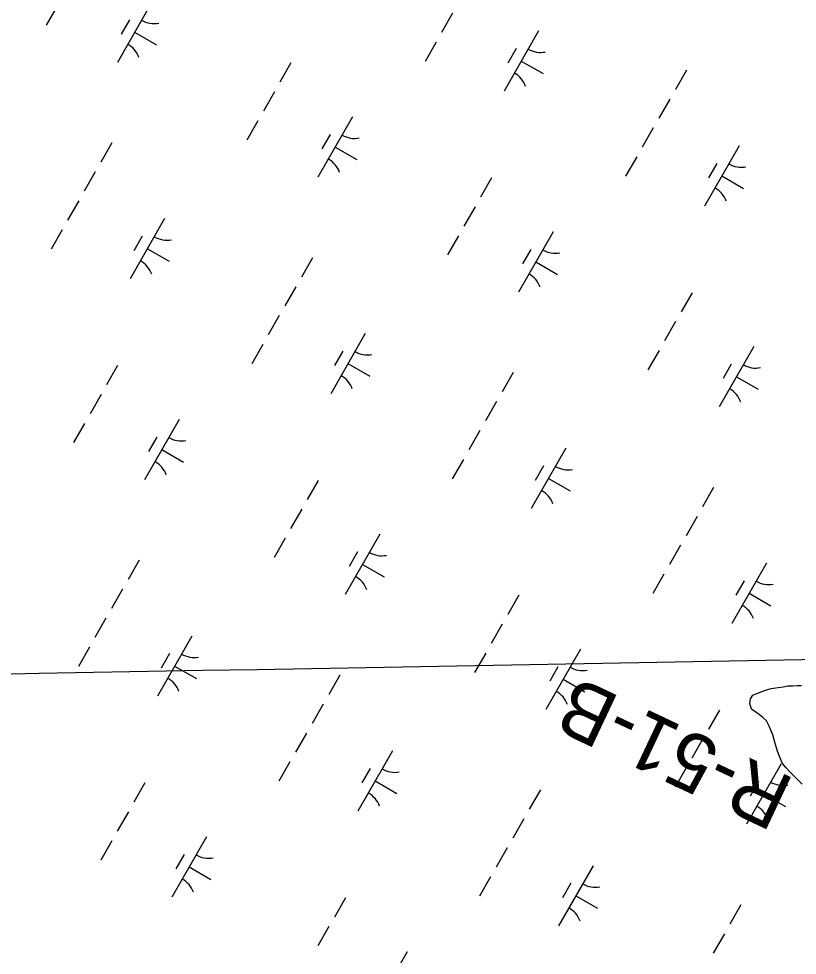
# Model space of a CAD drawing. Extents: x 3930721 to 3950824, y 220441 to 242861.
# Drawn here: x 3938703 to 3939263, y 229978 to 230653 of the extents above; entities that cross this region are included whole.
import ezdxf

# ---------------------------------------------------------------- set-up
doc = ezdxf.new("R2010")
doc.units = 0
for name, color, linetype in [('V-GRID-MAJR', 7, 'Continuous'), ('V-RIVR-RANG-IDEN', 7, 'Continuous'), ('V-TOPO-SHOR', 7, 'Continuous'), ('V-WETL-SWMP', 7, 'Continuous')]:
    doc.layers.add(name, color=color, linetype=linetype)

msp = doc.modelspace()

# ---------------------------------------------------------------- linework, layer by layer
at = {"layer": 'V-GRID-MAJR'}
msp.add_spline([(3935736.57, 230127.92), (3940756.95, 230218.14), (3946078.33, 230314.51), (3946614.64, 230324.26)], degree=3, dxfattribs=at)
at = {"layer": 'V-TOPO-SHOR'}
msp.add_lwpolyline([(3939263.36, 230104.8), (3939260.47, 230107.63), (3939257.84, 230110.21), (3939254.95, 230113.3), (3939252.32, 230116.39), (3939250.19, 230121.57), (3939248.58, 230125.97), (3939247.24, 230130.12), (3939246.43, 230133.49), (3939245.35, 230137.12), (3939244.02, 230140.48), (3939242.69, 230143.33), (3939240.83, 230147.21), (3939238.21, 230149.52), (3939235.85, 230151.58), (3939233.23, 230153.37), (3939230.09, 230155.68), (3939228.75, 230159.57), (3939229.23, 230162.95), (3939231.03, 230165.57), (3939235.17, 230167.43), (3939239.31, 230169.03), (3939244.24, 230170.38), (3939247.61, 230170.93), (3939252.8, 230171.77), (3939256.17, 230172.32), (3939259.81, 230172.36), (3939262.93, 230172.65), (3939266.05, 230172.68)], dxfattribs=at)
at = {"layer": 'V-WETL-SWMP'}
for p, q in [((3938730.49, 230661.75), (3938722.54, 230647.87)), ((3938798.61, 230664.56), (3938773.76, 230621.17)), ((3939015, 230656.64), (3939007.04, 230642.75)), ((3938782.48, 230651.91), (3938776.51, 230641.5)), ((3938786.19, 230642.87), (3938801.81, 230633.92)), ((3939076.82, 230643.79), (3939051.97, 230600.4)), ((3939003.07, 230635.81), (3938995.12, 230621.92)), ((3939060.68, 230631.13), (3939054.72, 230620.72)), ((3939064.4, 230622.09), (3939080.02, 230613.15)), ((3938898.69, 230620.74), (3938890.74, 230606.85)), ((3939183.19, 230615.62), (3939175.24, 230601.74)), ((3938886.76, 230599.91), (3938878.81, 230586.03)), ((3939171.26, 230594.8), (3939163.31, 230580.91)), ((3938942.95, 230581.9), (3938918.11, 230538.51)), ((3938874.83, 230579.08), (3938866.88, 230565.2)), ((3939159.34, 230573.97), (3939151.39, 230560.08)), ((3938926.82, 230569.24), (3938920.85, 230558.83)), ((3938769.79, 230563.19), (3938761.84, 230549.3)), ((3939221.16, 230561.12), (3939196.31, 230517.73)), ((3938930.53, 230560.2), (3938946.15, 230551.26)), ((3939147.41, 230553.14), (3939139.46, 230539.26)), ((3939205.03, 230548.47), (3939199.06, 230538.06)), ((3938757.86, 230542.36), (3938749.91, 230528.47)), ((3939043.03, 230538.07), (3939035.08, 230524.19)), ((3939208.74, 230539.43), (3939224.36, 230530.48)), ((3938745.94, 230521.53), (3938737.98, 230507.65)), ((3939031.1, 230517.24), (3939023.15, 230503.36)), ((3938807.76, 230508.69), (3938782.91, 230465.3)), ((3938734.01, 230500.71), (3938726.06, 230486.82)), ((3938791.62, 230496.03), (3938785.66, 230485.62)), ((3939019.17, 230496.42), (3939011.22, 230482.53)), ((3939087.3, 230499.23), (3939062.45, 230455.84)), ((3938795.34, 230486.99), (3938810.96, 230478.05)), ((3939071.16, 230486.58), (3939065.19, 230476.16)), ((3938914.13, 230480.52), (3938906.18, 230466.63)), ((3939074.87, 230477.54), (3939090.49, 230468.59)), ((3938902.2, 230459.69), (3938894.25, 230445.81)), ((3939187.37, 230455.4), (3939179.42, 230441.52)), ((3938890.28, 230438.87), (3938882.32, 230424.98)), ((3939175.44, 230434.58), (3939167.49, 230420.69)), ((3938952.1, 230426.02), (3938927.25, 230382.63)), ((3938878.35, 230418.04), (3938870.4, 230404.16)), ((3938935.97, 230413.37), (3938930, 230402.95)), ((3939163.52, 230413.75), (3939155.56, 230399.87)), ((3939231.64, 230416.56), (3939206.79, 230373.18)), ((3938773.97, 230402.97), (3938766.02, 230389.08)), ((3938939.68, 230404.33), (3938955.3, 230395.38)), ((3939215.5, 230403.91), (3939209.54, 230393.5)), ((3939058.47, 230397.85), (3939050.52, 230383.97)), ((3939219.21, 230394.87), (3939234.83, 230385.92)), ((3938762.04, 230382.14), (3938754.09, 230368.26)), ((3939046.55, 230377.03), (3939038.59, 230363.14)), ((3938750.11, 230361.32), (3938742.16, 230347.43)), ((3938818.24, 230364.13), (3938793.39, 230320.74)), ((3938802.1, 230351.48), (3938796.13, 230341.06)), ((3939034.62, 230356.2), (3939026.67, 230342.32)), ((3938805.81, 230342.43), (3938821.43, 230333.49)), ((3939096.44, 230343.35), (3939071.6, 230299.96)), ((3939022.69, 230335.37), (3939014.74, 230321.49)), ((3939080.31, 230330.7), (3939074.34, 230320.29)), ((3938918.31, 230320.3), (3938910.36, 230306.42)), ((3939084.02, 230321.66), (3939099.64, 230312.71)), ((3939202.81, 230315.19), (3939194.86, 230301.3)), ((3938906.38, 230299.48), (3938898.43, 230285.59)), ((3939190.89, 230294.36), (3939182.94, 230280.48)), ((3938894.46, 230278.65), (3938886.5, 230264.76)), ((3938962.58, 230281.46), (3938937.73, 230238.07)), ((3939178.96, 230273.53), (3939171.01, 230259.65)), ((3938946.44, 230268.81), (3938940.48, 230258.4)), ((3938789.41, 230262.75), (3938781.46, 230248.87)), ((3938950.15, 230259.77), (3938965.77, 230250.82)), ((3939240.79, 230260.69), (3939215.94, 230217.3)), ((3939167.03, 230252.71), (3939159.08, 230238.82)), ((3939224.65, 230248.03), (3939218.68, 230237.62)), ((3938777.49, 230241.92), (3938769.53, 230228.04)), ((3939062.65, 230237.64), (3939054.7, 230223.75)), ((3939228.36, 230238.99), (3939243.98, 230230.05)), ((3938765.56, 230221.1), (3938757.61, 230207.21)), ((3939050.72, 230216.81), (3939042.77, 230202.93)), ((3938827.38, 230208.25), (3938802.54, 230164.86)), ((3938753.63, 230200.27), (3938745.68, 230186.39)), ((3939106.92, 230198.8), (3939082.07, 230155.41)), ((3938811.25, 230195.6), (3938805.28, 230185.18)), ((3939038.8, 230195.98), (3939030.84, 230182.1)), ((3938814.96, 230186.56), (3938830.58, 230177.61)), ((3939090.78, 230186.14), (3939084.82, 230175.73)), ((3938933.75, 230180.08), (3938925.8, 230166.2)), ((3939094.49, 230177.1), (3939110.11, 230168.16)), ((3939239.31, 230169.03), (3939244.24, 230170.38)), ((3939244.24, 230170.38), (3939247.61, 230170.93)), ((3939247.61, 230170.93), (3939252.8, 230171.77)), ((3939252.8, 230171.77), (3939256.18, 230172.32)), ((3939256.18, 230172.32), (3939259.81, 230172.36)), ((3939259.81, 230172.36), (3939262.93, 230172.65)), ((3939262.93, 230172.65), (3939266.05, 230172.68)), ((3939228.75, 230159.57), (3939229.23, 230162.95)), ((3939229.23, 230162.95), (3939231.03, 230165.57)), ((3939231.03, 230165.57), (3939235.17, 230167.43)), ((3939235.17, 230167.43), (3939239.31, 230169.03)), ((3938921.83, 230159.26), (3938913.88, 230145.37)), ((3939230.09, 230155.68), (3939228.75, 230159.57)), ((3939206.99, 230154.97), (3939199.04, 230141.09)), ((3939233.23, 230153.37), (3939230.09, 230155.68)), ((3939235.85, 230151.58), (3939233.23, 230153.37)), ((3939238.21, 230149.52), (3939235.85, 230151.58)), ((3939240.83, 230147.21), (3939238.21, 230149.52)), ((3939242.69, 230143.33), (3939240.83, 230147.21)), ((3939244.02, 230140.48), (3939242.69, 230143.33)), ((3938909.9, 230138.43), (3938901.95, 230124.55)), ((3939245.35, 230137.12), (3939244.02, 230140.48)), ((3939246.43, 230133.49), (3939245.35, 230137.12)), ((3939195.07, 230134.14), (3939187.11, 230120.26)), ((3939247.24, 230130.12), (3939246.43, 230133.49)), ((3939248.58, 230125.97), (3939247.24, 230130.12)), ((3938971.73, 230125.58), (3938946.88, 230082.2)), ((3939250.19, 230121.57), (3939248.58, 230125.97)), ((3938897.97, 230117.61), (3938890.02, 230103.72)), ((3939251.26, 230116.13), (3939226.41, 230072.74)), ((3939252.32, 230116.39), (3939250.19, 230121.57)), ((3939254.95, 230113.3), (3939252.32, 230116.39)), ((3938955.59, 230112.93), (3938949.62, 230102.52)), ((3939183.14, 230113.32), (3939175.19, 230099.43)), ((3939257.84, 230110.21), (3939254.95, 230113.3)), ((3939266.51, 230101.72), (3939257.84, 230110.21)), ((3938793.59, 230102.53), (3938785.64, 230088.65)), ((3938959.3, 230103.89), (3938974.92, 230094.94)), ((3939235.12, 230103.48), (3939229.16, 230093.06)), ((3939078.1, 230097.42), (3939070.14, 230083.53)), ((3939238.84, 230094.44), (3939254.46, 230085.49)), ((3938781.66, 230081.71), (3938773.71, 230067.82)), ((3939066.17, 230076.59), (3939058.22, 230062.71)), ((3938837.86, 230063.69), (3938813.01, 230020.31)), ((3938769.74, 230060.88), (3938761.78, 230047)), ((3939054.24, 230055.77), (3939046.29, 230041.88)), ((3938821.72, 230051.04), (3938815.76, 230040.63)), ((3938825.43, 230042), (3938841.05, 230033.05)), ((3939116.07, 230042.92), (3939091.22, 229999.53)), ((3939042.31, 230034.94), (3939034.36, 230021.06)), ((3939099.93, 230030.27), (3939093.97, 230019.85)), ((3939103.64, 230021.22), (3939119.26, 230012.28)), ((3938937.93, 230019.87), (3938929.98, 230005.98)), ((3939222.44, 230014.75), (3939214.49, 230000.87)), ((3938926.01, 229999.04), (3938918.05, 229985.16)), ((3939210.51, 229993.93), (3939202.56, 229980.04)), ((3938982.2, 229981.03), (3938957.35, 229937.64))]:
    msp.add_line(p, q, dxfattribs=at)
for centre, start, end in [((3938800.12, 230666.72), 239.42788, 280.97154), ((3938772.67, 230618.78), 19.42788, 60.97154), ((3939078.33, 230645.94), 239.42788, 280.97154), ((3939050.88, 230598.01), 19.42788, 60.97154), ((3938944.46, 230584.05), 239.42788, 280.97154), ((3938917.01, 230536.12), 19.42788, 60.97154), ((3939222.67, 230563.28), 239.42788, 280.97154), ((3939195.22, 230515.34), 19.42788, 60.97154), ((3938809.27, 230510.84), 239.42788, 280.97154), ((3939088.8, 230501.39), 239.42788, 280.97154), ((3938781.82, 230462.9), 19.42788, 60.97154), ((3939061.35, 230453.45), 19.42788, 60.97154), ((3938953.61, 230428.18), 239.42788, 280.97154), ((3939233.15, 230418.72), 239.42788, 280.97154), ((3938926.16, 230380.24), 19.42788, 60.97154), ((3939205.69, 230370.78), 19.42788, 60.97154), ((3938819.74, 230366.28), 239.42788, 280.97154), ((3938792.29, 230318.35), 19.42788, 60.97154), ((3939097.95, 230345.51), 239.42788, 280.97154), ((3939070.5, 230297.57), 19.42788, 60.97154), ((3938964.09, 230283.62), 239.42788, 280.97154), ((3938936.63, 230235.68), 19.42788, 60.97154), ((3939242.29, 230262.84), 239.42788, 280.97154), ((3939214.84, 230214.91), 19.42788, 60.97154), ((3938828.89, 230210.41), 239.42788, 280.97154), ((3939108.43, 230200.95), 239.42788, 280.97154), ((3938801.44, 230162.47), 19.42788, 60.97154), ((3939080.97, 230153.01), 19.42788, 60.97154), ((3938973.23, 230127.74), 239.42788, 280.97154), ((3939252.77, 230118.29), 239.42788, 280.97154), ((3938945.78, 230079.8), 19.42788, 60.97154), ((3939225.31, 230070.35), 19.42788, 60.97154), ((3938839.37, 230065.85), 239.42788, 280.97154), ((3938811.91, 230017.91), 19.42788, 60.97154), ((3939117.58, 230045.08), 239.42788, 280.97154), ((3939090.12, 229997.14), 19.42788, 60.97154)]:
    msp.add_arc(centre, 17.62, start, end, dxfattribs=at)

# ---------------------------------------------------------------- texts
at = {"layer": 'V-RIVR-RANG-IDEN'}
msp.add_text('R-51-B', height=41.5, rotation=154.7751, dxfattribs=at).set_placement((3939262.46, 230104.77))

doc.saveas('drawing.dxf')
